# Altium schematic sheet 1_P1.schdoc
size 307 x 218 mm; Symbol: Drawing-Symbol_A4; Device: Drawing-Symbol_A4; Company: 嘉立创EDA; Version: V1.0; Page Size: A4; @Project Name: 超声波; @Page Count: 1; @Update Date: 2025-03-03; @Create Date: 2025-03-01; @Schematic Name: Schematic1; @Page No: 1; @Page Name: P1; @Create Time: 07:48:12; @Update Time: 21:02:19; Width: 1170; Height: 825; Region Start: 1; X Region Count: 6; Y Region Count: 4; Blade Width: 10; Title Block Position: 3; @Board Name: Board1
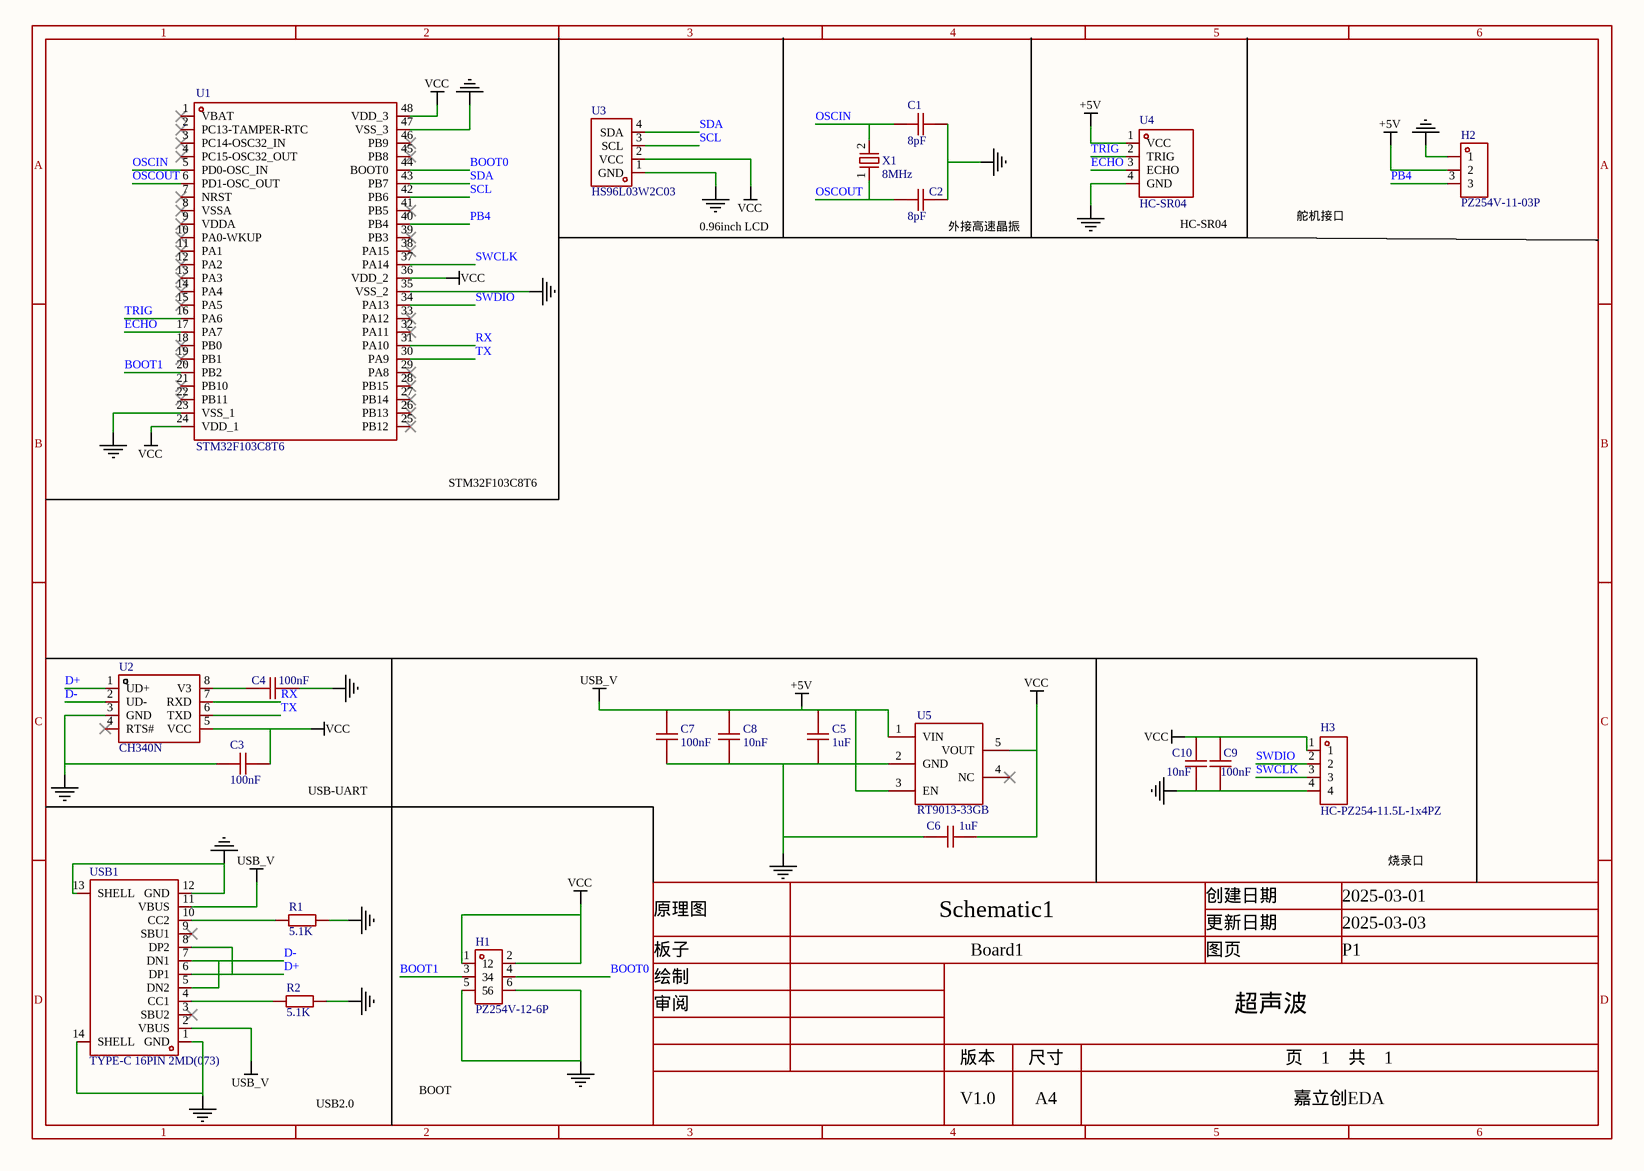
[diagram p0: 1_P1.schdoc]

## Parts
C1  8pF  [C0603]
C2  8pF  [C0603]
C3  100nF  [C0603]
C4  100nF  [C0603]
C5  1uF  [C0603]
C6  1uF  [C0603]
C7  100nF  [C0603]
C8  10nF  [C0603]
C9  100nF  [C0603]
C10  10nF  [C0603]
H1  PZ254V-12-6P  [HDR-TH_6P-P2.54-V-M-R2-C3-S2.54]
H2  PZ254V-11-03P  [HDR-TH_3P-P2.54-V-M]
H3  HC-PZ254-11.5L-1x4PZ  [HDR-TH_4P-P2.54-V-M]
R1  5.1K  [R0603]
R2  5.1K  [R0603]
U1  STM32F103C8T6  [LQFP-48_L7.0-W7.0-P0.50-LS9.0-BL]
U2  CH340N  [SOP-8_L4.9-W3.9-P1.27-LS6.0-BL]
U3  HS96L03W2C03  [OLED-TH_L27.8-W27.2-P2.54_C9900033791]
U4  HC-SR04  [TH_HC-SR04V]
U5  RT9013-33GB  [SOT-23-5_L3.0-W1.7-P0.95-LS2.8-BL]
USB1  TYPE-C 16PIN 2MD(073)  [USB-C-SMD_TYPE-C-6PIN-2MD-073]
X1  8MHz  [OSC-SMD_2P-L3.2-W2.5]

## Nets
+5V: C5.2 C7.2 C8.2 H2.2 U4.1(VCC) U5.1(VIN) U5.3(EN) USB1.2(VBUS) USB1.11(VBUS)  [also labelled USB_V]
GND: C1.2 C2.2 C3.1 C4.2 C5.1 C6.1 C7.1 C8.1 C9.1 C10.1 H1.5 H1.6 H2.1 H3.4 R1.2 R2.2 U1.23(VSS_1) U1.35(VSS_2) U1.47(VSS_3) U2.3(GND) U3.1(GND) U4.4(GND) U5.2(GND) USB1.1(GND) USB1.12(GND) USB1.13(SHELL) USB1.14(SHELL)
VCC: C3.2 C6.2 C9.2 C10.2 H1.1 H1.2 H3.1 U1.24(VDD_1) U1.36(VDD_2) U1.48(VDD_3) U2.5(VCC) U3.2(VCC) U5.5(VOUT)
BOOT0: H1.4 U1.44(BOOT0)
BOOT1: H1.3 U1.20(PB2)
D+: U2.1(UD+) USB1.6(DP1) USB1.8(DP2)
D-: U2.2(UD-) USB1.5(DN2) USB1.7(DN1)
ECHO: U1.17(PA7) U4.3(ECHO)
OSCIN: C1.1 U1.5(PD0-OSC_IN) X1.2(GND)
OSCOUT: C2.1 U1.6(PD1-OSC_OUT) X1.1
PB4: H2.3 U1.40(PB4)
RX: U1.31(PA10) U2.7(RXD)
SCL: U1.42(PB6) U3.3(SCL)
SDA: U1.43(PB7) U3.4(SDA)
SWCLK: H3.3 U1.37(PA14)
SWDIO: H3.2 U1.34(PA13)
TRIG: U1.16(PA6) U4.2(TRIG)
TX: U1.30(PA9) U2.6(TXD)
NetC4_1: C4.1 U2.8(V3)
NetR1_1: R1.1 USB1.10(CC2)
NetR2_1: R2.1 USB1.4(CC1)

Not connected (* = marked no-connect by the designer): U1 1(VBAT)* 2(PC13-TAMPER-RTC)* 3(PC14-OSC32_IN)* 4(PC15-OSC32_OUT)* 7(NRST)* 8(VSSA)* 9(VDDA)* 10(PA0-WKUP)* 11(PA1)* 12(PA2)* 13(PA3)* 14(PA4)* 15(PA5)* 18(PB0)* 19(PB1)* 21(PB10)* 22(PB11)* 25(PB12)* 26(PB13)* 27(PB14)* 28(PB15)* 29(PA8)* 32(PA11)* 33(PA12)* 38(PA15)* 39(PB3)* 41(PB5)* 45(PB8)* 46(PB9)*; U2 4(RTS#)*; U5 4(NC)*; USB1 3(SBU2)* 9(SBU1)*

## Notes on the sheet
- 0.96inch LCD
- (near C2) 外接高速晶振
- (near U4) HC-SR04
- 舵机接口
- STM32F103C8T6
- USB-UART
- 烧录口
- USB2.0
- BOOT

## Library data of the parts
C1-C10 = CAP_0603: Symbol: CapAcitance; Convert to PCB: yes
H1 = PZ254V-12-6P: Manufacturer: XFCN(兴飞); Add into BOM: yes; Pin Structure: 2x3P; Pitch: 2.54mm; Circluar Pins/Square Pins: 方针
H2 = PZ254V-11-03P: Manufacturer: XFCN(兴飞); Symbol: PZ254V-11-03P_C2937625; Add into BOM: yes; Pin Structure: 1x3P; Pitch: 2.54mm; Circluar Pins/Square Pins: 方针; Current Rating (Max): 3A; Voltage Rating (Max): 250V
H3 = HC-PZ254-11.5L-1x4PZ: Manufacturer: HC(虹成电子); Add into BOM: yes; Pin Structure: 1x4P; Pitch: 2.54mm; Circluar Pins/Square Pins: 方针; Current Rating: 3A
R1 R2 = Res_0603: Symbol: 电阻; Convert to PCB: yes
U1 = STM32F103C8T6: Manufacturer: ST(意法半导体); Add into BOM: yes; CPU Core: ARM-M3; CPU Maximum Speed: 72MHz; Program Storage Size: 64KB; Program Memory Type: FLASH; Number of I/O: 37; ADC (Bit): 12bit; Low Voltage Detection Threshold: 2V~3.6V
U2 = CH340N: Manufacturer: WCH(南京沁恒); Symbol: CH340N_C2977777; Add into BOM: yes; Applications Function: USB转串口; Protocol: USB 2.0; Number of Channels: 1; Voltage - Supply: 3.3V；5V; Data Rate: 2Mbps
U3 = HS96L03W2C03: Manufacturer: HS(汉昇); Add into BOM: yes; Main Control Chip: SSD1315; Interface Type: I2C; Pixel Resolution: 128x64
U4 = HC-SR04: Manufacturer: Universal Microelectronics; Add into BOM: yes
U5 = RT9013-33GB: Manufacturer: RICHTEK(立锜); Add into BOM: yes; Output Type: 固定; Maximum Input Voltage: 5.5V; Output Voltage: 3.3V; Output Current: 500mA; Power Supply Rejection Ratio (PSRR): 50dB@(10kHz); Dropout Voltage: 400mV@(500mA); standby current: 50uA; Output Polarity: 正极; Number of Outputs: 1
USB1 = TYPE-C 16PIN 2MD(073): Manufacturer: SHOU HAN(首韩); Add into BOM: yes; Gender: 母; Number of Contacts: 16P; Number of Ports: 1; Current Rating - Power (Max): 5A; Rated Voltage (Max): 5V; Connect-Disconnect Life: 5千次; Core Colour: 黑色
X1 = NX3225GD-8MHZ-STD-CRA-3: Manufacturer: NDK; Add into BOM: yes; Normal temperature Frequency Tolerance: ±50ppm; External load capacitor: 8pF; Frequency Stability(Full temperature range): ±150ppm; Equivalent Series Resistance (ESR): 500Ω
